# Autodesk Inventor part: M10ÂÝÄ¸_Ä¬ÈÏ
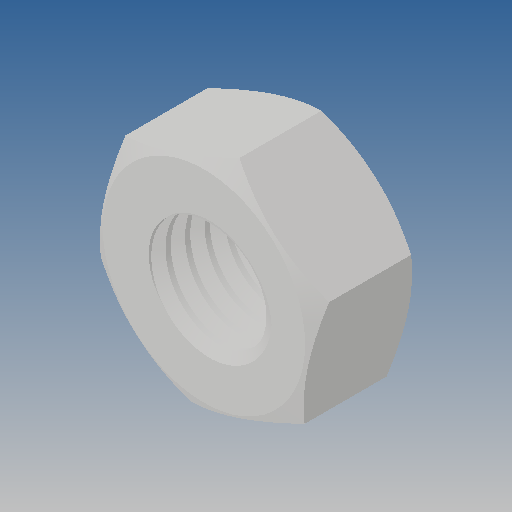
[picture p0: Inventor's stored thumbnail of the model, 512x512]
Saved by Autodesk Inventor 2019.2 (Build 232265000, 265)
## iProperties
Created: 2010-06
Part Number: M10ÂÝÄ¸_Ä¬ÈÏ
Material: Ogólny
Document SubType Name: Modeling
Designer: CADENGINEERING4
Density: 1 g/cm^3
Appearance: Domyślna
Author: CADENGINEERING4
Revision Number: ÈÎºÎ
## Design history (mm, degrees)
feature "NONE"
node "Bryła1"
